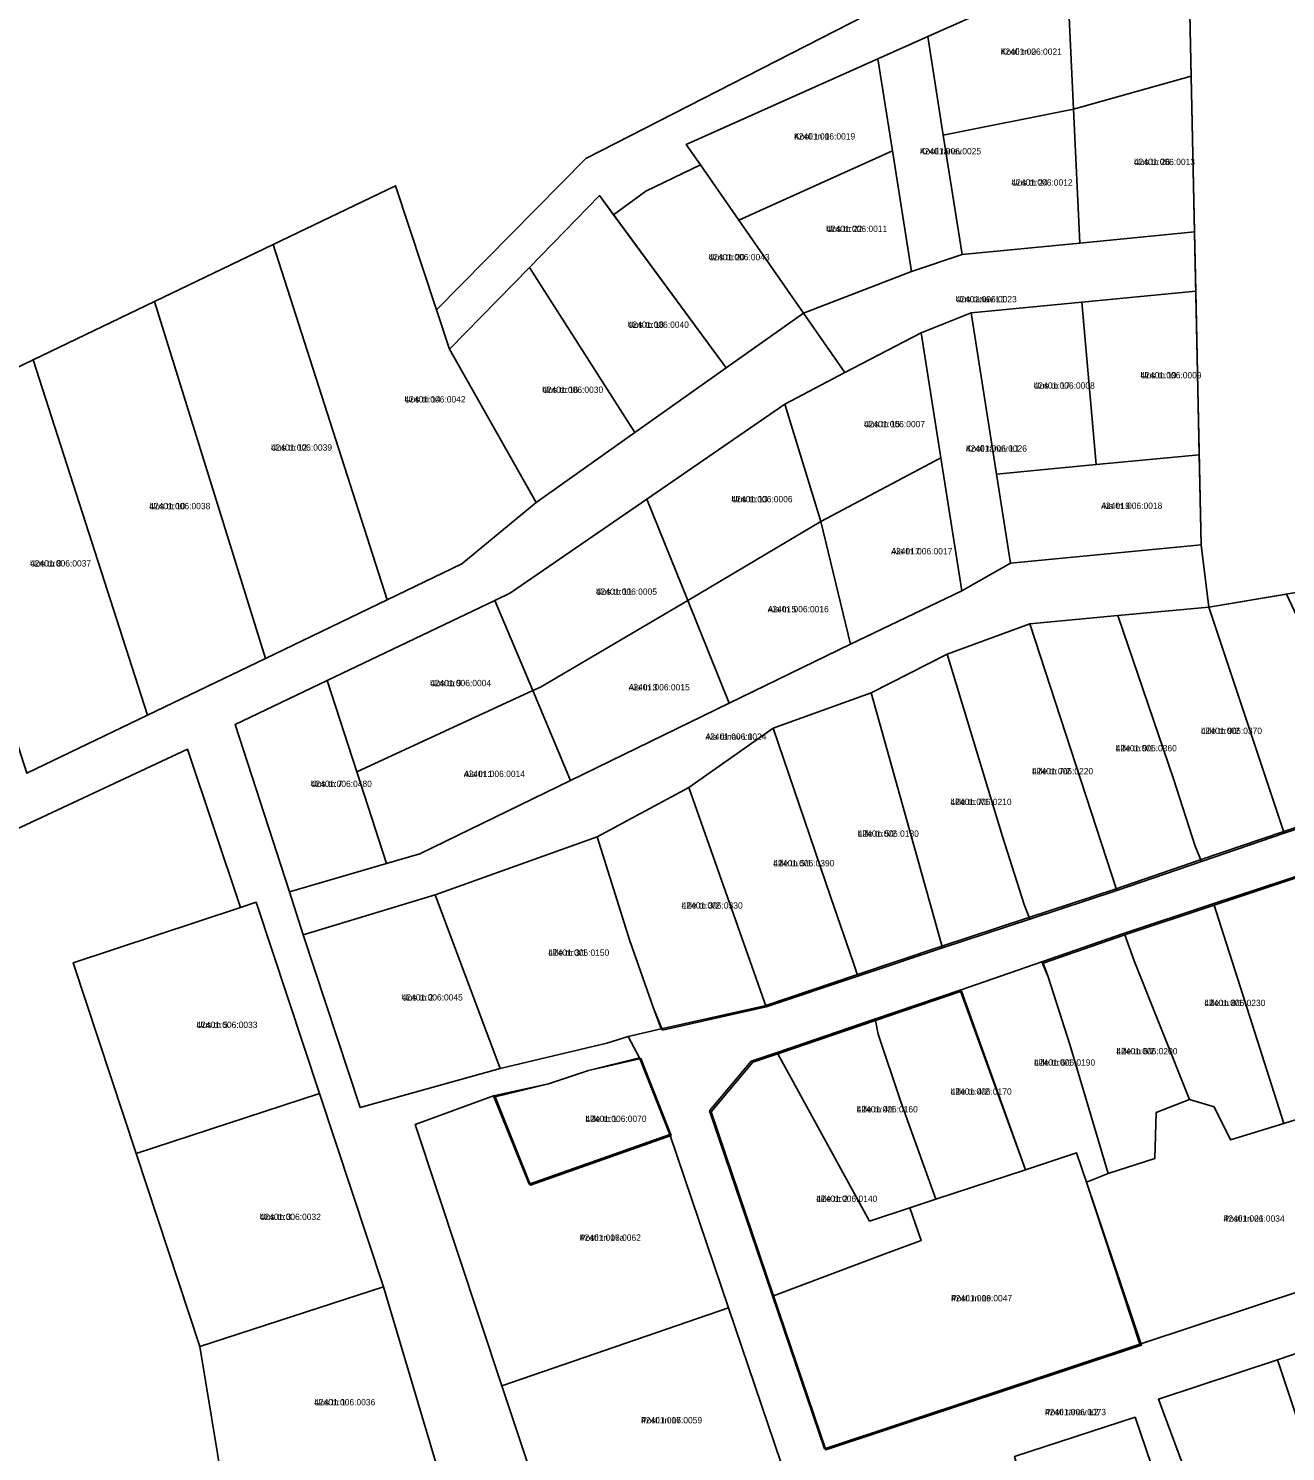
# Model space of a CAD drawing. Extents: x 595979 to 597983, y 6604231 to 6607350.
# Drawn here: x 597213 to 597511.5, y 6606558.1 to 6606896.1 of the extents above; entities that cross this region are included whole.
import ezdxf

# ---------------------------------------------------------------- set-up
doc = ezdxf.new("R2010")
doc.units = 0
for name, color, linetype in [('L_AADRESS', 7, 'Continuous'), ('PIIR', 7, 'Continuous'), ('TUNNUS', 7, 'Continuous')]:
    doc.layers.add(name, color=color, linetype=linetype)

msp = doc.modelspace()

# ---------------------------------------------------------------- linework, layer by layer
at = {"layer": 'PIIR'}
for points in [[(597017.44, 6606900.77), (597227.14, 6607031), (597472.32, 6607193.03), (597483.18, 6607186.71), (597483.37, 6607176.6), (597401.98, 6607123.23), (597433.56, 6606911.97), (597488.02, 6606934.96), (597488.27, 6606921.71), (597459.63, 6606908.91), (597426.55, 6606894.12), (597414.73, 6606888.84), (597369.21, 6606868.49), (597372.57, 6606863.67), (597359.62, 6606857.46), (597351.95, 6606851.81), (597348.63, 6606856.37), (597331.97, 6606839.29), (597312.99, 6606819.9), (597309.9, 6606829.23), (597345.38, 6606865.19), (597415.02, 6606900.83), (597380.8, 6607108.42), (597047.73, 6606904.01)], [(597212.63, 6606719.19), (597241.28, 6606732.97), (597269.28, 6606746.45), (597298.23, 6606760.38), (597315.93, 6606768.9), (597333.55, 6606783.47), (597356.99, 6606800.09), (597378.7, 6606815.46), (597397.07, 6606828.45), (597406.9, 6606814.33), (597392.62, 6606806.88), (597359.84, 6606784.31), (597327.5, 6606762.04), (597323.73, 6606760.24), (597283.99, 6606741.24), (597262.08, 6606730.77), (597274.99, 6606691.04), (597278.28, 6606680.81), (597291.77, 6606639.81), (597325.04, 6606649.08), (597350.37, 6606655.07), (597355.46, 6606656.66), (597358.13, 6606651.64), (597345.97, 6606648.61), (597336.5, 6606645.44), (597323.48, 6606642.58), (597304.86, 6606635.78), (597325.44, 6606573.72), (597337.5, 6606537.33)], [(597310.56, 6606552.82), (597297.3, 6606597.25), (597282.13, 6606643.15), (597267.13, 6606688.55), (597263.39, 6606687.31), (597250.77, 6606724.9), (597172.79, 6606688.42)], [(597172.79, 6606688.42), (597250.77, 6606724.9), (597263.39, 6606687.31), (597223.69, 6606674.18), (597238.63, 6606628.88), (597253.73, 6606583.05), (597260.71, 6606540.89)], [(597391.78, 6606555.36), (597379.23, 6606592.26), (597365.32, 6606633.43), (597358.13, 6606651.64), (597355.46, 6606656.66), (597363.27, 6606658.52), (597387.86, 6606663.94), (597409.6, 6606671.28), (597429.66, 6606678.04), (597450.35, 6606684.85), (597471.08, 6606691.7), (597491.2, 6606698.62), (597510.84, 6606705.27), (597531.97, 6606712.38)], [(597541.38, 6606590.75), (597509.62, 6606579.92), (597481.32, 6606570.54), (597503.02, 6606512.14)], [(597490.98, 6606521.6), (597475.79, 6606566.26), (597447.13, 6606556.9)]]:
    msp.add_lwpolyline(points, dxfattribs=at)
for points in [[(597756.25, 6607029.31), (597555.1, 6606895.13), (597595.03, 6606781.37), (597596.23, 6606778.19), (597573.92, 6606775.05), (597536, 6606765.81), (597493.26, 6606758.6), (597491.45, 6606773.47), (597488.27, 6606921.71), (597488.02, 6606934.96), (597483.37, 6607176.6), (597483.18, 6607186.71)], [(597185.54, 6606803.62), (597168.46, 6606801.45), (597157.16, 6606852.69), (597127.58, 6606861.69), (597047.73, 6606904.01), (597380.8, 6607108.42), (597415.02, 6606900.83), (597345.38, 6606865.19), (597309.9, 6606829.23), (597300.15, 6606858.7), (597271.1, 6606844.74), (597243, 6606831.24), (597214.14, 6606817.36)], [(597488.27, 6606921.71), (597489.06, 6606884.73), (597461.14, 6606876.87), (597459.63, 6606908.91)], [(597459.63, 6606908.91), (597461.14, 6606876.87), (597430.24, 6606870.71), (597426.55, 6606894.12)], [(597418.17, 6606867.01), (597414.73, 6606888.84), (597426.55, 6606894.12), (597430.24, 6606870.71), (597434.69, 6606842.41), (597422.68, 6606838.34)], [(597414.73, 6606888.84), (597418.17, 6606867.01), (597381.7, 6606850.54), (597372.57, 6606863.67), (597369.21, 6606868.49)], [(597489.06, 6606884.73), (597489.85, 6606847.75), (597462.63, 6606845.11), (597461.14, 6606876.87)], [(597461.14, 6606876.87), (597462.63, 6606845.11), (597434.69, 6606842.41), (597430.24, 6606870.71)], [(597418.17, 6606867.01), (597422.68, 6606838.34), (597397.07, 6606828.45), (597381.7, 6606850.54)], [(597359.62, 6606857.46), (597372.57, 6606863.67), (597381.7, 6606850.54), (597397.07, 6606828.45), (597378.7, 6606815.46), (597351.95, 6606851.81)], [(597300.15, 6606858.7), (597312.99, 6606819.9), (597333.55, 6606783.47), (597315.93, 6606768.9), (597298.23, 6606760.38), (597271.1, 6606844.74)], [(597348.63, 6606856.37), (597378.7, 6606815.46), (597356.99, 6606800.09), (597331.97, 6606839.29)], [(597424.98, 6606823.75), (597406.9, 6606814.33), (597397.07, 6606828.45), (597422.68, 6606838.34), (597434.69, 6606842.41), (597462.63, 6606845.11), (597489.85, 6606847.75), (597490.16, 6606833.71), (597463.11, 6606831.09), (597436.87, 6606828.56)], [(597271.1, 6606844.74), (597298.23, 6606760.38), (597269.28, 6606746.45), (597243, 6606831.24)], [(597331.97, 6606839.29), (597356.99, 6606800.09), (597333.55, 6606783.47), (597312.99, 6606819.9)], [(597490.16, 6606833.71), (597490.99, 6606794.84), (597466.54, 6606792.48), (597463.11, 6606831.09)], [(597243, 6606831.24), (597269.28, 6606746.45), (597241.28, 6606732.97), (597214.14, 6606817.36)], [(597463.11, 6606831.09), (597466.54, 6606792.48), (597442.91, 6606790.19), (597436.87, 6606828.56)], [(597429.64, 6606794.09), (597424.98, 6606823.75), (597436.87, 6606828.56), (597442.91, 6606790.19), (597446.23, 6606769.1), (597434.61, 6606762.54)], [(597406.9, 6606814.33), (597424.98, 6606823.75), (597429.64, 6606794.09), (597401.14, 6606778.99), (597392.62, 6606806.88)], [(597214.14, 6606817.36), (597241.28, 6606732.97), (597212.63, 6606719.19), (597185.54, 6606803.62)], [(597392.62, 6606806.88), (597401.14, 6606778.99), (597369.57, 6606760.21), (597359.84, 6606784.31)], [(597429.64, 6606794.09), (597434.61, 6606762.54), (597408.21, 6606749.84), (597401.14, 6606778.99)], [(597466.54, 6606792.48), (597490.99, 6606794.84), (597491.45, 6606773.47), (597446.23, 6606769.1), (597442.91, 6606790.19)], [(597327.5, 6606762.04), (597359.84, 6606784.31), (597369.57, 6606760.21), (597334.58, 6606739.66), (597332.77, 6606738.82), (597323.73, 6606760.24)], [(597401.14, 6606778.99), (597408.21, 6606749.84), (597379.43, 6606735.83), (597369.57, 6606760.21)], [(597298.06, 6606697.77), (597305.96, 6606700.07), (597341.77, 6606717.5), (597379.43, 6606735.83), (597408.21, 6606749.84), (597434.61, 6606762.54), (597446.23, 6606769.1), (597491.45, 6606773.47), (597493.26, 6606758.6), (597471.65, 6606756.62), (597450.8, 6606754.71), (597431.19, 6606747.46), (597413.15, 6606738.3), (597389.86, 6606729.89), (597369.8, 6606715.77), (597348.05, 6606704.09), (597309.58, 6606690.28), (597278.28, 6606680.81), (597274.99, 6606691.04)], [(597283.99, 6606741.24), (597323.73, 6606760.24), (597332.77, 6606738.82), (597291.02, 6606719.5)], [(597334.58, 6606739.66), (597369.57, 6606760.21), (597379.43, 6606735.83), (597341.77, 6606717.5), (597332.77, 6606738.82)], [(597511.76, 6606761.71), (597525.92, 6606731.59), (597531.35, 6606715.69), (597532.28, 6606712.08), (597511.17, 6606704.98), (597493.26, 6606758.6)], [(597471.65, 6606756.62), (597484.86, 6606717.9), (597490.07, 6606701.91), (597491.56, 6606698.27), (597471.44, 6606691.38), (597450.8, 6606754.71)], [(597484.86, 6606717.9), (597471.65, 6606756.62), (597493.26, 6606758.6), (597511.17, 6606704.98), (597491.56, 6606698.27), (597490.07, 6606701.91)], [(597449.43, 6606688.04), (597444.29, 6606704.14), (597431.19, 6606747.46), (597450.8, 6606754.71), (597471.44, 6606691.38), (597450.76, 6606684.55)], [(597413.15, 6606738.3), (597431.19, 6606747.46), (597444.29, 6606704.14), (597449.43, 6606688.04), (597450.76, 6606684.55), (597430.02, 6606677.71)], [(597262.08, 6606730.77), (597283.99, 6606741.24), (597291.02, 6606719.5), (597298.06, 6606697.77), (597274.99, 6606691.04)], [(597341.77, 6606717.5), (597305.96, 6606700.07), (597298.06, 6606697.77), (597291.02, 6606719.5), (597332.77, 6606738.82)], [(597403.56, 6606689.66), (597389.86, 6606729.89), (597413.15, 6606738.3), (597430.02, 6606677.71), (597409.96, 6606671.02), (597408.86, 6606674.31)], [(597389.86, 6606729.89), (597403.56, 6606689.66), (597408.86, 6606674.31), (597409.96, 6606671.02), (597388.18, 6606663.75), (597369.8, 6606715.77)], [(597361.46, 6606663.38), (597355.84, 6606679.38), (597348.05, 6606704.09), (597369.8, 6606715.77), (597388.18, 6606663.75), (597363.6, 6606658.21)], [(597384.66, 6606650.83), (597374.77, 6606639.01), (597389.6, 6606595.35), (597402.03, 6606558.78), (597476.94, 6606583.64), (597530.15, 6606601.23), (597591.43, 6606621.52), (597606.41, 6606626.45), (597593.33, 6606665.34), (597576.47, 6606715.76), (597553.04, 6606707.89), (597535.82, 6606702.03), (597516.63, 6606695.54), (597494.23, 6606688.14), (597473.02, 6606681.13), (597453.62, 6606674.41), (597434.23, 6606667.71), (597413.88, 6606660.78), (597390.59, 6606652.82)], [(597309.58, 6606690.28), (597348.05, 6606704.09), (597355.84, 6606679.38), (597361.46, 6606663.38), (597363.27, 6606658.52), (597355.46, 6606656.66), (597350.37, 6606655.07), (597325.04, 6606649.08)], [(597495.6, 6606684.59), (597494.52, 6606687.87), (597516.88, 6606695.3), (597530.34, 6606645.73), (597517.56, 6606638.05), (597511.06, 6606636.01), (597500.75, 6606668.57)], [(597223.69, 6606674.18), (597263.39, 6606687.31), (597267.13, 6606688.55), (597282.13, 6606643.15), (597238.63, 6606628.88)], [(597309.58, 6606690.28), (597325.04, 6606649.08), (597291.77, 6606639.81), (597278.28, 6606680.81)], [(597473.36, 6606680.83), (597494.52, 6606687.87), (597495.6, 6606684.59), (597500.75, 6606668.57), (597511.06, 6606636.01), (597498.4, 6606632.17), (597494.58, 6606640), (597488.73, 6606641.73), (597475.57, 6606674.64)], [(597460.31, 6606654.78), (597455.1, 6606670.84), (597453.94, 6606674.11), (597473.36, 6606680.83), (597475.57, 6606674.64), (597488.73, 6606641.73), (597480.81, 6606638.66), (597480.46, 6606627.66), (597469.38, 6606624.1)], [(597434.23, 6606667.71), (597453.62, 6606674.41), (597455.1, 6606670.84), (597460.31, 6606654.78), (597469.38, 6606624.1), (597464.23, 6606622.07), (597461.9, 6606629.02), (597449.77, 6606625.04)], [(597420.18, 6606641.14), (597414.75, 6606657.23), (597414.18, 6606660.47), (597434.56, 6606667.4), (597449.77, 6606625.04), (597428.43, 6606618.02)], [(597414.18, 6606660.47), (597414.75, 6606657.23), (597420.18, 6606641.14), (597428.43, 6606618.02), (597422.32, 6606615.99), (597412.69, 6606612.85), (597390.94, 6606652.57)], [(597336.5, 6606645.44), (597345.97, 6606648.61), (597358.43, 6606651.41), (597365.62, 6606633.19), (597332.24, 6606621.36), (597323.82, 6606642.32)], [(597385, 6606650.56), (597390.94, 6606652.57), (597412.69, 6606612.85), (597422.32, 6606615.99), (597425, 6606608.26), (597416.87, 6606605.2), (597389.94, 6606595.1), (597375.13, 6606638.79)], [(597238.63, 6606628.88), (597282.13, 6606643.15), (597297.3, 6606597.25), (597253.73, 6606583.05)], [(597304.86, 6606635.78), (597323.48, 6606642.58), (597331.9, 6606621.62), (597365.32, 6606633.43), (597379.23, 6606592.26), (597325.44, 6606573.72)], [(597464.23, 6606622.07), (597469.38, 6606624.1), (597480.46, 6606627.66), (597480.81, 6606638.66), (597488.73, 6606641.73), (597494.58, 6606640), (597498.4, 6606632.17), (597511.06, 6606636.01), (597517.56, 6606638.05), (597530.15, 6606601.23), (597476.94, 6606583.64)], [(597416.87, 6606605.2), (597425, 6606608.26), (597422.32, 6606615.99), (597428.43, 6606618.02), (597449.77, 6606625.04), (597461.9, 6606629.02), (597464.23, 6606622.07), (597477.28, 6606583.36), (597402.32, 6606558.51), (597389.94, 6606595.1)], [(597297.3, 6606597.25), (597310.56, 6606552.82), (597260.71, 6606540.89), (597253.73, 6606583.05)], [(597325.44, 6606573.72), (597379.23, 6606592.26), (597391.78, 6606555.36), (597337.5, 6606537.33)], [(597509.62, 6606579.92), (597541.36, 6606590.73), (597561.14, 6606532.48), (597529.16, 6606521.4)], [(597503.02, 6606512.14), (597481.32, 6606570.54), (597509.62, 6606579.92), (597529.16, 6606521.4)], [(597456.39, 6606524.74), (597447.13, 6606556.9), (597475.79, 6606566.26), (597490.98, 6606521.6), (597460.45, 6606510.21), (597440.14, 6606505.19), (597438.63, 6606510.78), (597436.81, 6606516.67), (597434.89, 6606518)]]:
    msp.add_lwpolyline(points, close=True, dxfattribs=at)

# ---------------------------------------------------------------- texts
at = {"layer": 'L_AADRESS'}
for s, p in [('Kooli tn 2', (597443.88, 6606889.81)), ('Kooli tn 1', (597394.82, 6606869.69)), ('Kooli tänav', (597424.71, 6606866.16)), ('Uus tn 26', (597475.5, 6606863.63)), ('Uus tn 24', (597446.44, 6606858.74)), ('Uus tn 22', (597402.43, 6606847.73)), ('Uus tn 20', (597374.51, 6606841.02)), ('Uus tänav L1', (597433.18, 6606831.04)), ('Uus tn 18', (597355.34, 6606824.97)), ('Uus tn 19', (597477.05, 6606812.97)), ('Uus tn 16', (597334.99, 6606809.52)), ('Uus tn 17', (597451.7, 6606810.52)), ('Uus tn 14', (597302.32, 6606807.24)), ('Uus tn 15', (597411.4, 6606801.37)), ('Uus tn 12', (597270.61, 6606795.8)), ('Kooli tänav L1', (597435.6, 6606795.57)), ('Uus tn 10', (597241.71, 6606781.9)), ('Uus tn 13', (597379.95, 6606783.54)), ('Aia tn 9', (597467.74, 6606781.97)), ('Uus tn 8', (597213.41, 6606768.29)), ('Aia tn 7', (597417.88, 6606771.17)), ('Uus tn 11', (597347.76, 6606761.57)), ('Aia tn 5', (597388.54, 6606757.41)), ('Uus tn 9', (597308.38, 6606739.87)), ('Aia tn 3', (597355.53, 6606738.86)), ('Lille tn 9/2', (597491.41, 6606728.53)), ('Aia tänav L1', (597373.76, 6606727.14)), ('Lille tn 9/1', (597471.18, 6606724.38)), ('Aia tn 1', (597316.42, 6606718.29)), ('Lille tn 7/2', (597451.31, 6606718.93)), ('Uus tn 7', (597280.07, 6606715.94)), ('Lille tn 7/1', (597431.95, 6606711.64)), ('Lille tn 5/2', (597409.94, 6606704.11)), ('Lille tn 5/1', (597389.88, 6606697.07)), ('Lille tn 3/2', (597368.11, 6606687.05)), ('Lille tn 3/1', (597336.43, 6606675.84)), ('Uus tn 2', (597301.66, 6606665.22)), ('Lille tn 8/1', (597492.21, 6606663.9)), ('Uus tn 5', (597252.91, 6606658.7)), ('Lille tn 6/1', (597451.8, 6606649.75)), ('Lille tn 6/2', (597471.33, 6606652.43)), ('Lille tn 4/2', (597431.98, 6606642.85)), ('Lille tn 1', (597345.28, 6606636.38)), ('Lille tn 4/1', (597409.68, 6606638.64)), ('Lille tn 2', (597400.07, 6606617.4)), ('Uus tn 3', (597267.96, 6606613.1)), ('Posti tn 21', (597496.78, 6606612.69)), ('Posti tn 17a', (597343.94, 6606608.15)), ('Posti tn 19', (597432.08, 6606593.77)), ('Uus tn 1', (597280.88, 6606569.07)), ('Posti tänav L2', (597454.37, 6606566.74)), ('Posti tn 17', (597358.48, 6606564.79))]:
    msp.add_text(s, height=1.5, dxfattribs=at).set_placement(p)
at = {"layer": 'TUNNUS'}
for s, p in [('42401:006:0021', (597443.88, 6606889.81)), ('42401:006:0019', (597394.82, 6606869.69)), ('42401:006:0025', (597424.71, 6606866.16)), ('42401:006:0013', (597475.5, 6606863.63)), ('42401:006:0012', (597446.44, 6606858.74)), ('42401:006:0011', (597402.43, 6606847.73)), ('42401:006:0043', (597374.51, 6606841.02)), ('42401:006:0023', (597433.18, 6606831.04)), ('42401:006:0040', (597355.34, 6606824.97)), ('42401:006:0009', (597477.05, 6606812.97)), ('42401:006:0030', (597334.99, 6606809.52)), ('42401:006:0008', (597451.7, 6606810.52)), ('42401:006:0042', (597302.32, 6606807.24)), ('42401:006:0007', (597411.4, 6606801.37)), ('42401:006:0039', (597270.61, 6606795.8)), ('42401:006:0026', (597435.6, 6606795.57)), ('42401:006:0038', (597241.71, 6606781.9)), ('42401:006:0006', (597379.95, 6606783.54)), ('42401:006:0018', (597467.74, 6606781.97)), ('42401:006:0037', (597213.41, 6606768.29)), ('42401:006:0017', (597417.88, 6606771.17)), ('42401:006:0005', (597347.76, 6606761.57)), ('42401:006:0016', (597388.54, 6606757.41)), ('42401:006:0004', (597308.38, 6606739.87)), ('42401:006:0015', (597355.53, 6606738.86)), ('42401:006:0370', (597491.41, 6606728.53)), ('42401:006:0024', (597373.76, 6606727.14)), ('42401:006:0360', (597471.18, 6606724.38)), ('42401:006:0014', (597316.42, 6606718.29)), ('42401:006:0220', (597451.31, 6606718.93)), ('42401:006:0480', (597280.07, 6606715.94)), ('42401:006:0210', (597431.95, 6606711.64)), ('42401:006:0180', (597409.94, 6606704.11)), ('42401:006:0390', (597389.88, 6606697.07)), ('42401:006:0330', (597368.11, 6606687.05)), ('42401:006:0150', (597336.43, 6606675.84)), ('42401:006:0045', (597301.66, 6606665.22)), ('42401:006:0230', (597492.21, 6606663.9)), ('42401:006:0033', (597252.91, 6606658.7)), ('42401:006:0190', (597451.8, 6606649.75)), ('42401:006:0200', (597471.33, 6606652.43)), ('42401:006:0170', (597431.98, 6606642.85)), ('42401:006:0070', (597345.28, 6606636.38)), ('42401:006:0160', (597409.68, 6606638.64)), ('42401:006:0140', (597400.07, 6606617.4)), ('42401:006:0032', (597267.96, 6606613.1)), ('42401:006:0034', (597496.78, 6606612.69)), ('42401:006:0062', (597343.94, 6606608.15)), ('42401:006:0047', (597432.08, 6606593.77)), ('42401:006:0036', (597280.88, 6606569.07)), ('42401:006:0073', (597454.37, 6606566.74)), ('42401:006:0059', (597358.48, 6606564.79))]:
    msp.add_text(s, height=1.5, dxfattribs=at).set_placement(p)

doc.saveas('drawing.dxf')
